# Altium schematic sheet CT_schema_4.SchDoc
size 573 x 363 mm
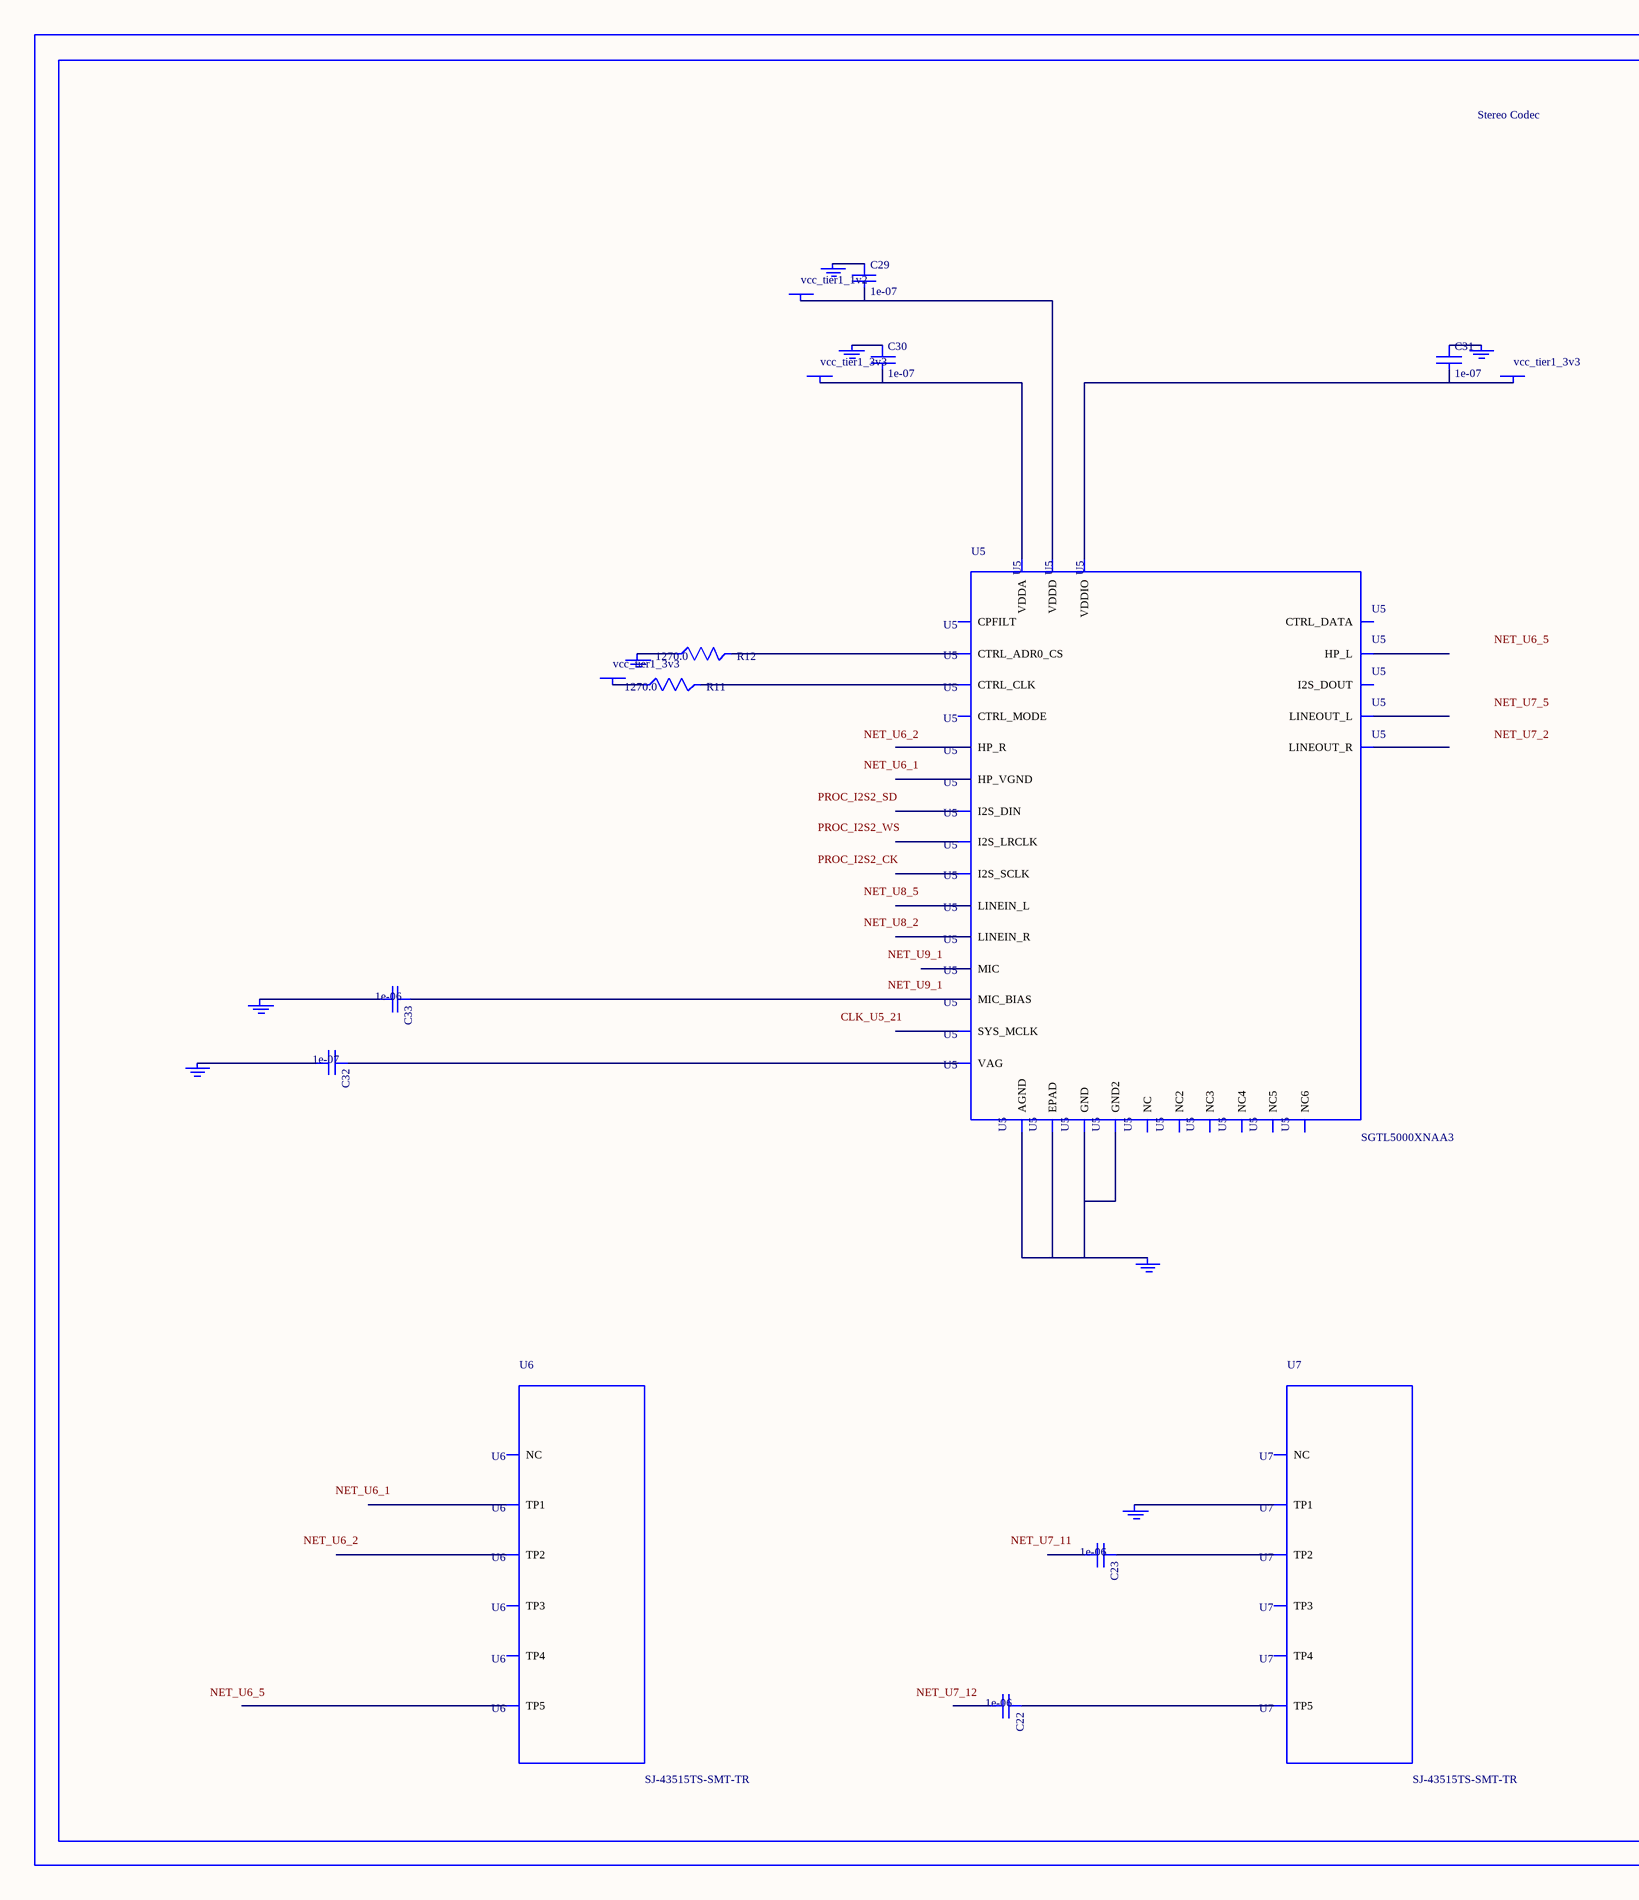
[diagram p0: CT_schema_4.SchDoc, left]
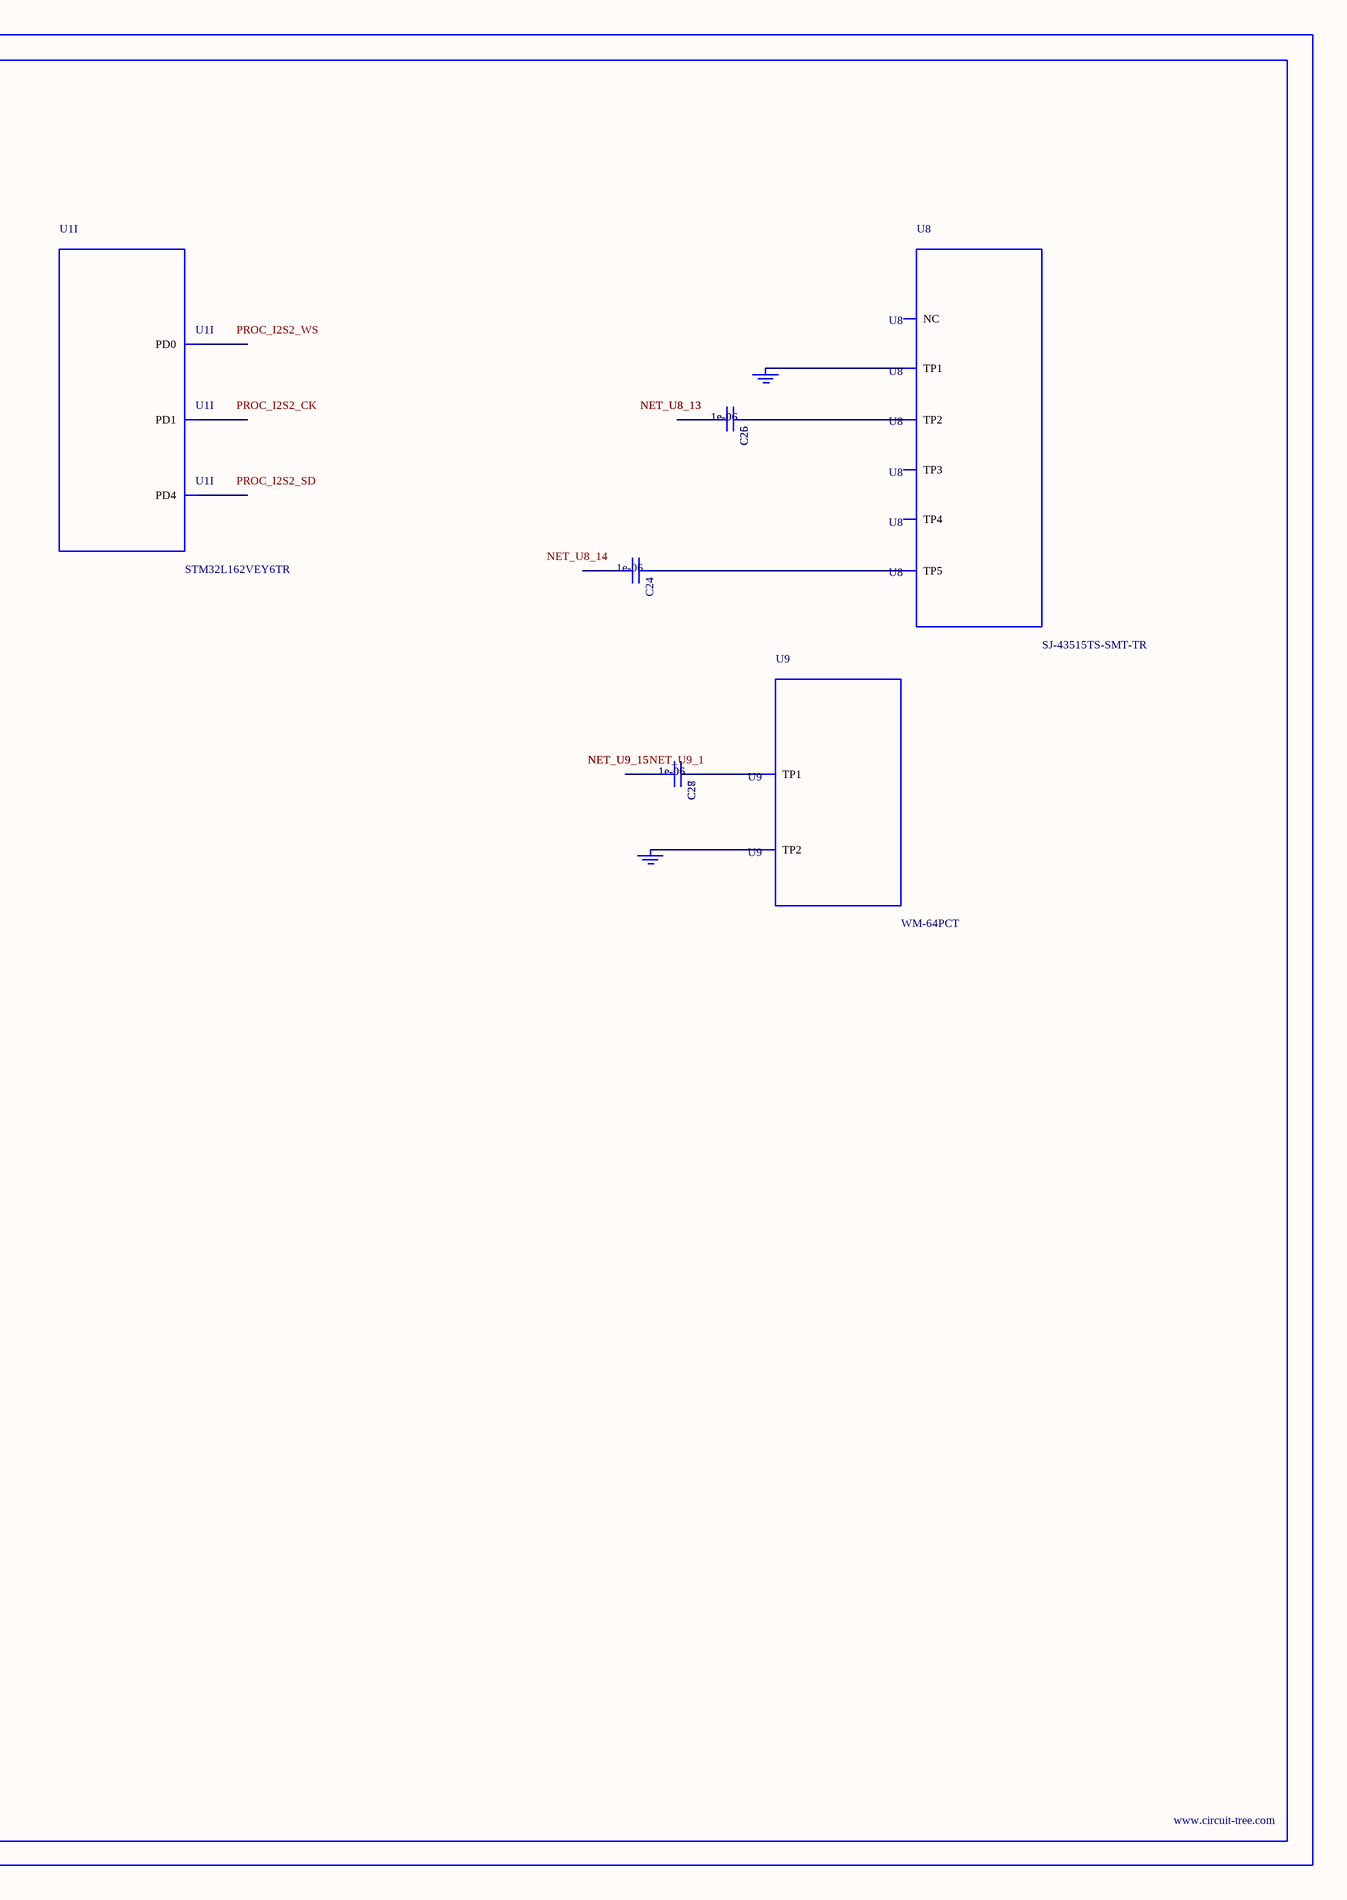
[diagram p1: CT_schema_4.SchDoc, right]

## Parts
BORDER3  (no value)
C22  1e-06  [C0603]
C23  1e-06  [C0603]
C24  1e-06  [C0603]
C25  1e-06  [C0603]
C26  1e-06  [C0603]
C27  1e-06  [C0603]
C28  1e-06  [C0603]
C29  1e-07  [C0402]
C30  1e-07  [C0402]
C31  1e-07  [C0402]
C32  1e-07  [C0402]
C33  1e-06  [C0603]
GND_INSTANCE_3_0  (no value)
GND_INSTANCE_3_1  (no value)
GND_INSTANCE_3_2  (no value)
GND_INSTANCE_3_3  (no value)
GND_INSTANCE_3_4  (no value)
GND_INSTANCE_3_5  (no value)
GND_INSTANCE_3_6  (no value)
GND_INSTANCE_3_7  (no value)
GND_INSTANCE_3_8  (no value)
GND_INSTANCE_3_9  (no value)
GND_INSTANCE_3_10  (no value)
POWER_INSTANCE_3_0  vcc_tier1_3v3
POWER_INSTANCE_3_1  vcc_tier1_3v3
POWER_INSTANCE_3_2  vcc_tier1_3v3
POWER_INSTANCE_3_3  vcc_tier1_1v2
R11  1270.0  [R0603]
R12  1270.0  [R0603]
U1  STM32L162VEY6TR  [WLCSP104]  (part I of 9)
U5  SGTL5000XNAA3  [QFN-32]
U6  SJ-43515TS-SMT-TR  [SJ-43515TS-SMT-TR]
U7  SJ-43515TS-SMT-TR  [SJ-43515TS-SMT-TR]
U8  SJ-43515TS-SMT-TR  [SJ-43515TS-SMT-TR]
U9  WM-64PCT  [WM-64PC]

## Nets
NetC22_1: C22.1 U7.5(TP5)
NetC23_1: C23.1 U7.2(TP2)
NetC24_1: C24.1 U8.5(TP5)
NetC25_1: C25.1 C26.1 U8.2(TP2)
NetC25_2: C25.2 C26.2
NetC27_1: C27.1 C28.1 U9.1(TP1)
NetC27_2: C27.2 C28.2
NetC29_1: C29.1 GND_INSTANCE_3_5.0(GND)
NetC29_2: C29.2 POWER_INSTANCE_3_3.0(PWR) U5.30(VDDD)
NetC30_1: C30.1 GND_INSTANCE_3_1.0(GND)
NetC30_2: C30.2 POWER_INSTANCE_3_0.0(PWR) U5.5(VDDA)
NetC31_1: C31.1 GND_INSTANCE_3_4.0(GND)
NetC31_2: C31.2 POWER_INSTANCE_3_1.0(PWR) U5.20(VDDIO)
NetC32_1: C32.1 U5.10(VAG)
NetC32_2: C32.2 GND_INSTANCE_3_2.0(GND)
NetC33_1: C33.1 U5.16(MIC_BIAS)
NetC33_2: C33.2 GND_INSTANCE_3_3.0(GND)
NetGND_INSTANCE_3_0_0: GND_INSTANCE_3_0.0(GND) U5.1(GND) U5.3(GND2) U5.7(AGND) U5.EXP(EPAD)
NetGND_INSTANCE_3_6_0: GND_INSTANCE_3_6.0(GND) R12.1
NetGND_INSTANCE_3_7_0: GND_INSTANCE_3_7.0(GND) U7.1(TP1)
NetGND_INSTANCE_3_8_0: GND_INSTANCE_3_8.0(GND) GND_INSTANCE_3_9.0(GND) U8.1(TP1)
NetGND_INSTANCE_3_10_0: GND_INSTANCE_3_10.0(GND) U9.2(TP2)
NetPOWER_INSTANCE_3_2_0: POWER_INSTANCE_3_2.0(PWR) R11.1
NetR11_2: R11.2 U5.29(CTRL_CLK)
NetR12_2: R12.2 U5.31(CTRL_ADR0_CS)

Not connected (* = marked no-connect by the designer): C22 2; C23 2; C24 2; U1 A2(PD0) A3(PD4) D4(PD1); U5 2(HP_R) 4(HP_VGND) 6(HP_L) 8(NC) 9(NC2) 11(LINEOUT_R) 12(LINEOUT_L) 13(LINEIN_R) 14(LINEIN_L) 15(MIC) 17(NC3) 18(CPFILT) 19(NC4) 21(SYS_MCLK) 22(NC5) 23(I2S_LRCLK) 24(I2S_SCLK) 25(I2S_DOUT) 26(I2S_DIN) 27(CTRL_DATA) 28(NC6) 32(CTRL_MODE); U6 1(TP1) 2(TP2) 3(TP3) 4(TP4) 5(TP5) 6(NC); U7 3(TP3) 4(TP4) 6(NC); U8 3(TP3) 4(TP4) 6(NC)

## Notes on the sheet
- Labels drawn without touching a wire or pin: CLK_U5_21, NET_U6_1, NET_U6_2, NET_U6_5, NET_U7_2, NET_U7_5, NET_U7_11, NET_U7_12, NET_U8_2, NET_U8_5, NET_U8_14, NET_U9_1, PROC_I2S2_CK, PROC_I2S2_SD, PROC_I2S2_WS

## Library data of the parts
BORDER3 = BORDER_PAGE3
C22-C28 C33 = C0603C105K3RACTU
C29-C32 = C0402C104K3RACTU
GND_INSTANCE_3_0-GND_INSTANCE_3_10 = GND
POWER_INSTANCE_3_0-POWER_INSTANCE_3_3 = PWR
R11 R12 = RC0603FR-071K27L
